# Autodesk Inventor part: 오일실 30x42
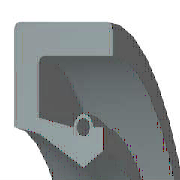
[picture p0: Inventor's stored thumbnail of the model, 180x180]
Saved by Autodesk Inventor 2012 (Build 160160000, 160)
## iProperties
IsCustomPart: 0
Company: 한국ATC센터
Created: 2009-02
Part Number: 오일실 30x42
Material: 고무
Description: 오일-실
Document SubType Name: Modeling
Standard: KS B 2804
Designer: KYOUNG IL JANG
Standards Organization: KS
Language: ko-KR
Size Designation: S - 30 42 8
Categories: <MemberInstance><Categories><Category DisplayName="샤프트 부품" InternalName="7f7aeb1f-a693-4053-b835-cee3144e0d98" Mnemonic="SHFT"><Category DisplayName="실링" Intern
Density: 0.93 g/cm^3
Author: KYOUNG IL JANG
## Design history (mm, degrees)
revolve "본체" stored, may be unused: angle "d17" = 90 deg
revolve "스프링1" stored, may be unused: angle "d18" = 90 deg
body "Solid1"
sketch "스케치1"
  geometry: L1 (0, 21)-(8, 21); L2 (8, 21)-(8, 19.75); L3 (8, 19.75)-(1.75, 19.75); L4 (0, 21)-(0, 17.1); L5 (0, 17.1)-(1.75, 16.75); L6 (1.75, 16.75)-(4.9, 15); L7 (4.9, 15)-(0, 15); L8 (6.3, 15.875)-(6.3, 17.1); L9 (0, 0)-(9.586, 0) reference; L10 (4.9, 15)-(6.3, 15.875); L11 (0, 18)-(0, -3) reference; L12 (-1.917, 0)-(11.503, 0) reference; L13 (4.2, 17.1)-(1.75, 17.59); L14 (1.75, 17.59)-(1.75, 19.75); L15 (6.3, 17.1)-(5.6, 17.1); C1 r 0.455 at (4.9, 17.1); A1 r 0.7 centre (4.9, 17.1) between (5.6, 17.1) and (4.2, 17.1)
  constraints: 26 end point, 5 horizontal alignment, 4 perpendicular, 2 centre point, 2 collinear, 2 horizontal, 2 parallel, 2 point on circle, 2 point on line, 2 vertical alignment, 1 coincident
  dimensions: "d0" = 42 diameter of L1 L9 (= SD2); "d1" = 31.75 diameter of L8.start L9 (= ABDM); "d2" = 1.25 distance of L1.end L2.end (computed from SD); "d3" = 0.91 diameter of C1 (= SPDI); "d4" = 1.4 diameter of A1 (= SPDA); "d5" = 30 diameter of L6.end L9 (= NND); "d6" = 33.5 diameter of L5.end L9 (= TKDM); "d7" = 34.2 diameter of L4.end L9 (= HLDM); "d8" = 4.9 distance from line of C1.centre L4 (= SPDST); "d9" = 6.3 distance between parallel lines of L8 L4 (= SDI); "d10" = 8 distance between parallel lines of L2 L4 (= SWDT); "d12" = 1.75 distance between parallel lines of L14 L4 (= SD)
fillet "모깎기1" dims "d11" = 0.4 (= RR)
other parameters: "SD2" = 42 [user parameter; used in 1 equation term], "SWDT" = 8 [user parameter; used in 1 equation term], "RR" = 0.4 [user parameter; used in 1 equation term], "SD" = 1.75 [user parameter; used in 2 equation terms], "NND" = 30 [user parameter; used in 1 equation term], "SPDA" = 1.4 [user parameter; used in 1 equation term], "SPDI" = 0.91 [user parameter; used in 1 equation term], "TKDM" = 33.5 [user parameter; used in 1 equation term], "HLDM" = 34.2 [user parameter; used in 1 equation term], "ABDM" = 31.75 [user parameter; used in 1 equation term], "SDI" = 6.3 [user parameter; used in 1 equation term], "SPDST" = 4.9 [user parameter; used in 1 equation term], "d13" = 0, "d14" = 0, "d15" = 0, "LAB" = 0.35 [user parameter]
